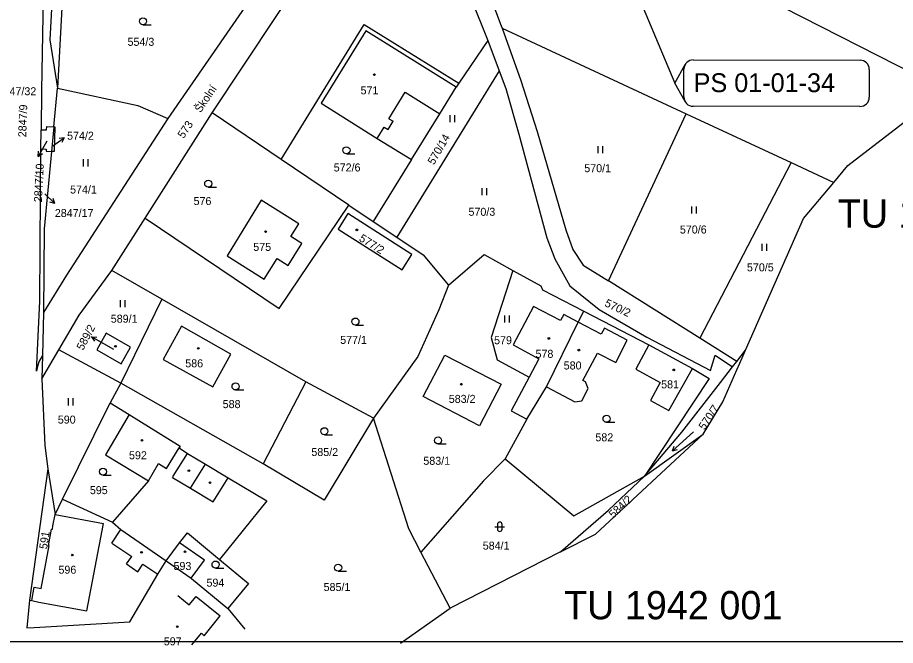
# Model space of a CAD drawing. Extents: x -558358 to -557517, y -1073785 to -1073189.
# Drawn here: x -558184.5 to -557998, y -1073784.9 to -1073651.5 of the extents above; entities that cross this region are included whole.
import ezdxf

# ---------------------------------------------------------------- set-up
doc = ezdxf.new("R2010")
doc.units = 0
for name, color, linetype in [('Hranice parcel', 7, 'Continuous'), ('Parcelní čísla', 7, 'Continuous'), ('Pop  PČ popisy', 7, 'Continuous'), ('Rozpiska_pole_1', 7, 'Continuous'), ('Rozpiska_pole_2', 7, 'Continuous'), ('Vnitřní kresba', 7, 'Continuous'), ('Vrstva 28', 7, 'Continuous'), ('Značky budov', 7, 'Continuous'), ('Značky kultur', 7, 'Continuous')]:
    doc.layers.add(name, color=color, linetype=linetype)

msp = doc.modelspace()

# ---------------------------------------------------------------- linework, layer by layer
at = {"layer": 'Hranice parcel'}
for p, q in [((-558126.57, -1073635.37), (-558152.59, -1073672.96)), ((-558047.53, -1073636.2), (-557987.38, -1073666.93)), ((-558083.83, -1073647.78), (-558081.75, -1073653.27)), ((-558081.75, -1073653.27), (-558081.56, -1073653.8)), ((-558081.56, -1073653.8), (-558042.48, -1073671.96)), ((-558084.61, -1073656.37), (-558090.78, -1073665.45)), ((-558084.61, -1073656.37), (-558082.19, -1073662.86)), ((-558082.19, -1073662.86), (-558103.95, -1073698.19)), ((-558082.19, -1073662.86), (-558080.79, -1073666.61)), ((-558090.78, -1073665.45), (-558091.34, -1073666.27)), ((-558176.83, -1073674.75), (-558176.05, -1073666.5)), ((-558008.13, -1073682.96), (-557987.38, -1073666.93)), ((-558157.39, -1073694.14), (-558143.16, -1073671.79)), ((-558128.54, -1073681.64), (-558143.16, -1073671.79)), ((-558058.98, -1073707.44), (-558042.48, -1073671.96)), ((-558042.48, -1073671.96), (-558020.18, -1073682.32)), ((-558178.3, -1073674.68), (-558176.83, -1073674.75)), ((-558176.83, -1073674.75), (-558177.33, -1073679.98)), ((-558176.83, -1073674.75), (-558176.6, -1073674.76)), ((-558176.6, -1073674.76), (-558176.71, -1073680)), ((-558179.54, -1073679.43), (-558179.49, -1073675.4)), ((-558178.45, -1073679.93), (-558177.33, -1073679.98)), ((-558176.71, -1073680), (-558177.33, -1073679.98)), ((-558114.13, -1073691.34), (-558128.54, -1073681.64)), ((-558100.81, -1073681.69), (-558108.93, -1073694.83)), ((-558020.18, -1073682.32), (-558039.55, -1073719.63)), ((-558020.18, -1073682.32), (-558011.11, -1073686.54)), ((-558011.11, -1073686.54), (-558008.13, -1073682.96)), ((-558017.53, -1073694.23), (-558011.11, -1073686.54)), ((-558114.13, -1073691.34), (-558108.93, -1073694.83)), ((-558164.46, -1073705.23), (-558157.39, -1073694.14)), ((-558108.93, -1073694.83), (-558103.95, -1073698.19)), ((-558029.85, -1073722.15), (-558017.53, -1073694.23)), ((-558153.86, -1073711.3), (-558164.46, -1073705.23)), ((-558079.26, -1073705.23), (-558083.89, -1073719.49)), ((-558039.55, -1073719.63), (-558058.98, -1073707.44)), ((-558153.86, -1073711.3), (-558162.58, -1073729.18)), ((-558123.29, -1073728.86), (-558153.86, -1073711.3)), ((-558178.98, -1073714.16), (-558179.23, -1073723.31)), ((-558065.38, -1073716.24), (-558064.19, -1073713.89)), ((-558064.19, -1073713.89), (-558050.38, -1073721.04)), ((-558072.16, -1073729.98), (-558065.38, -1073716.24)), ((-558083.89, -1073719.49), (-558082.62, -1073724.25)), ((-558031.72, -1073724.54), (-558039.55, -1073719.63)), ((-558050.38, -1073721.04), (-558041.12, -1073726.03)), ((-558179.37, -1073728.25), (-558175.74, -1073722.09)), ((-558179.23, -1073723.31), (-558179.37, -1073728.25)), ((-558162.58, -1073729.18), (-558175.74, -1073722.09)), ((-558031.72, -1073724.54), (-558029.85, -1073722.15)), ((-558082.62, -1073724.25), (-558075.83, -1073727.93)), ((-558032.62, -1073725.69), (-558031.72, -1073724.54)), ((-558162.58, -1073729.18), (-558164.87, -1073733.32)), ((-558132.34, -1073746.32), (-558162.58, -1073729.18)), ((-558123.29, -1073728.86), (-558132.34, -1073746.32)), ((-558108.92, -1073736.57), (-558123.29, -1073728.86)), ((-558076.28, -1073736.83), (-558072.16, -1073729.98)), ((-558174.95, -1073753.84), (-558164.87, -1073733.32)), ((-558164.87, -1073733.32), (-558160.79, -1073735.84)), ((-558076.28, -1073736.83), (-558080.95, -1073745.27)), ((-558061.7, -1073761.21), (-558038.85, -1073740)), ((-558051.32, -1073748.93), (-558043.37, -1073739.61)), ((-558051.32, -1073748.93), (-558038.85, -1073740)), ((-558080.95, -1073745.27), (-558085.52, -1073749.88)), ((-558178.08, -1073747.39), (-558181.97, -1073775.25)), ((-558178.08, -1073747.39), (-558176.52, -1073757.07)), ((-558058.99, -1073756.15), (-558051.32, -1073748.93)), ((-558085.52, -1073749.88), (-558098.82, -1073765.08)), ((-558176.52, -1073757.07), (-558174.95, -1073753.84)), ((-558174.95, -1073753.84), (-558164.36, -1073758.7)), ((-558069.16, -1073765.01), (-558058.99, -1073756.15)), ((-558069.16, -1073765.01), (-558061.7, -1073761.21)), ((-558152.96, -1073766.88), (-558150.14, -1073763.05)), ((-558092.62, -1073776.97), (-558098.82, -1073765.08)), ((-558069.16, -1073765.01), (-558092.62, -1073776.97)), ((-558152.96, -1073766.88), (-558147.64, -1073770.59)), ((-558147.64, -1073770.59), (-558147.54, -1073770.67)), ((-558147.54, -1073770.67), (-558139.85, -1073777.06)), ((-558181.97, -1073775.25), (-558182.51, -1073781.13)), ((-558139.85, -1073777.06), (-558136.25, -1073781.43)), ((-558103.16, -1073784.41), (-558092.62, -1073776.97)), ((-558182.51, -1073781.13), (-558181.01, -1073781.05))]:
    msp.add_line(p, q, dxfattribs=at)
for points in [[(-558086.19, -1073392.25), (-558100.56, -1073410.01), (-558117.51, -1073431.08), (-558131.78, -1073449.27), (-558138.48, -1073457.68), (-558143.38, -1073464.02), (-558146.99, -1073468.89), (-558150.46, -1073473.83), (-558152.02, -1073476.41), (-558154.26, -1073480.97), (-558156.46, -1073486.6), (-558158.91, -1073494.31), (-558160.3, -1073500.48), (-558162.16, -1073510.4), (-558165.76, -1073536.46), (-558169.94, -1073565.43), (-558173.74, -1073591.61), (-558177.66, -1073620.33), (-558178.51, -1073631.87), (-558179.02, -1073643), (-558179.24, -1073655.12), (-558179.45, -1073666.94), (-558179.49, -1073675.4)], [(-558175.82, -1073622.18), (-558177.63, -1073656.22), (-558176.05, -1073666.5)], [(-558175.82, -1073622.18), (-558174.18, -1073632.38), (-558176.05, -1073666.5)], [(-558143.16, -1073671.79), (-558122.68, -1073640.91), (-558116.74, -1073631.82), (-558110.18, -1073623.69)], [(-558110.18, -1073623.69), (-558095.16, -1073631.27), (-558088.2, -1073647.35), (-558084.61, -1073656.37)], [(-558128.54, -1073681.64), (-558110.84, -1073652.98), (-558090.78, -1073665.45)], [(-558091.34, -1073666.27), (-558110.52, -1073654.36), (-558120.01, -1073669.73), (-558108.1, -1073677.21), (-558100.81, -1073681.69)], [(-558081.56, -1073653.8), (-558077.6, -1073664.88), (-558074.09, -1073675.7), (-558068.03, -1073696.59), (-558066.56, -1073700.76), (-558064.34, -1073704.08), (-558058.98, -1073707.44)], [(-558176.05, -1073666.5), (-558158.95, -1073670.2), (-558152.59, -1073672.96)], [(-558100.81, -1073681.69), (-558094.8, -1073671.95), (-558091.34, -1073666.27)], [(-558080.79, -1073666.61), (-558077.98, -1073676.29), (-558072.03, -1073698.27), (-558070.37, -1073702.74), (-558067.15, -1073708.5), (-558060.97, -1073713.55), (-558050.8, -1073719.38), (-558037.27, -1073726.47), (-558036.33, -1073723.21), (-558032.62, -1073725.69)], [(-558152.59, -1073672.96), (-558174.12, -1073706.25), (-558178.98, -1073714.16)], [(-558179.49, -1073675.4), (-558178.35, -1073675.4), (-558178.3, -1073674.68)], [(-558180.47, -1073726.64), (-558179.79, -1073711.73), (-558179.61, -1073688.81), (-558179.54, -1073679.43)], [(-558179.54, -1073679.43), (-558178.44, -1073679.44), (-558178.45, -1073679.93)], [(-558177.33, -1073679.98), (-558178.88, -1073696.38), (-558178.98, -1073714.16)], [(-558157.39, -1073694.14), (-558128.92, -1073713.32), (-558114.13, -1073691.34)], [(-558124.75, -1073695.3), (-558132.74, -1073690.28), (-558139.98, -1073702.13), (-558132.13, -1073707.05), (-558129.35, -1073702.69), (-558127, -1073704.15), (-558124.1, -1073699.49), (-558126.45, -1073698.03), (-558124.75, -1073695.3)], [(-558114.32, -1073693.16), (-558116.42, -1073696.46), (-558102.81, -1073705.11), (-558100.72, -1073701.82), (-558114.32, -1073693.16)], [(-558103.95, -1073698.19), (-558098.36, -1073701.95), (-558092.97, -1073708.36)], [(-558092.97, -1073708.36), (-558085.4, -1073701.82), (-558079.26, -1073705.23)], [(-558175.74, -1073722.09), (-558171.39, -1073714.72), (-558164.46, -1073705.23)], [(-558079.26, -1073705.23), (-558073.37, -1073708.51), (-558073.01, -1073709.33), (-558064.19, -1073713.89)], [(-558092.97, -1073708.36), (-558095.02, -1073713.61), (-558099.46, -1073723.54), (-558108.92, -1073736.57)], [(-558065.38, -1073716.24), (-558068.48, -1073714.62), (-558069.13, -1073715.86), (-558074.89, -1073712.87), (-558079.25, -1073721.04), (-558073.73, -1073723.99), (-558075.83, -1073727.93)], [(-558072.16, -1073729.98), (-558066.15, -1073733.15), (-558064.66, -1073732.92), (-558063.26, -1073730.33), (-558063.88, -1073728.9), (-558064.4, -1073728.63), (-558061.31, -1073722.78), (-558057.44, -1073724.76), (-558054.98, -1073720.06), (-558059.84, -1073717.49), (-558060.51, -1073718.77), (-558065.38, -1073716.24)], [(-558139.17, -1073722.99), (-558149.67, -1073717.07), (-558153.56, -1073724.14), (-558143.05, -1073729.97), (-558139.17, -1073722.99)], [(-558160.49, -1073721.53), (-558165.71, -1073718.57), (-558167.69, -1073722.06), (-558162.47, -1073725.03), (-558160.49, -1073721.53)], [(-558050.38, -1073721.04), (-558053.17, -1073726.18), (-558047.96, -1073729.01), (-558050.05, -1073732.86), (-558046.14, -1073734.98), (-558041.12, -1073726.03)], [(-558179.23, -1073723.31), (-558179.97, -1073724.66), (-558180.29, -1073725.65), (-558180.47, -1073726.64)], [(-558081.79, -1073729.39), (-558086.39, -1073738.22), (-558098.32, -1073732.01), (-558093.7, -1073723.21), (-558081.79, -1073729.39)], [(-558031.69, -1073726.31), (-558031.08, -1073724.94), (-558029.85, -1073722.15)], [(-558041.12, -1073726.03), (-558037.61, -1073728.19), (-558051.32, -1073748.93)], [(-558043.37, -1073739.61), (-558035.2, -1073729), (-558032.62, -1073725.69)], [(-558038.85, -1073740), (-558034.7, -1073733.14), (-558031.69, -1073726.31)], [(-558179.37, -1073728.25), (-558178.74, -1073742.4), (-558178.08, -1073747.39)], [(-558075.83, -1073727.93), (-558079.61, -1073735.04), (-558076.28, -1073736.83)], [(-558160.79, -1073735.84), (-558165.86, -1073744.39), (-558156.72, -1073749.9), (-558164.36, -1073758.7)], [(-558160.79, -1073735.84), (-558149.94, -1073742.55), (-558150.18, -1073742.93), (-558148.38, -1073744.09), (-558144.55, -1073746.39), (-558139.78, -1073749.25), (-558131.58, -1073754.18), (-558141.63, -1073766.63)], [(-558108.92, -1073736.57), (-558119.39, -1073754.05), (-558132.34, -1073746.32)], [(-558098.82, -1073765.08), (-558101.41, -1073760.13), (-558108.92, -1073736.57)], [(-558080.95, -1073745.27), (-558066.32, -1073757.38), (-558051.32, -1073748.93)], [(-558181.97, -1073775.25), (-558181.48, -1073775.34), (-558180.95, -1073772.5), (-558179.48, -1073772.78), (-558177.77, -1073763.68), (-558177.92, -1073763.66), (-558177.27, -1073760.18), (-558177.12, -1073760.21), (-558177.05, -1073759.47), (-558176.52, -1073757.07)], [(-558164.36, -1073758.7), (-558162.58, -1073760.28), (-558152.96, -1073766.88)], [(-558150.14, -1073763.05), (-558148.43, -1073760.98), (-558141.63, -1073766.63)], [(-558147.64, -1073770.59), (-558144.77, -1073766.75), (-558150.14, -1073763.05)], [(-558181.01, -1073781.05), (-558160.65, -1073779.83), (-558154.69, -1073769.71), (-558152.96, -1073766.88)], [(-558141.63, -1073766.63), (-558135.48, -1073771.74), (-558139.85, -1073777.06)]]:
    msp.add_lwpolyline(points, dxfattribs=at)
at = {"layer": 'Pop  PČ popisy'}
for p, q in [((-558177.05, -1073678.78), (-558174.59, -1073677.06)), ((-558174.59, -1073677.06), (-558175.7, -1073677.22)), ((-558174.59, -1073677.06), (-558175.12, -1073678.04)), ((-558178.66, -1073678.4), (-558180.11, -1073681.02)), ((-558178.32, -1073677.78), (-558178.66, -1073678.4)), ((-558180.11, -1073681.02), (-558180.07, -1073679.91)), ((-558180.11, -1073681.02), (-558179.19, -1073680.39)), ((-558178.75, -1073688.95), (-558176.59, -1073691.03)), ((-558176.59, -1073691.03), (-558176.96, -1073689.98)), ((-558176.59, -1073691.03), (-558177.66, -1073690.7)), ((-558166.16, -1073720.8), (-558168.79, -1073719.34)), ((-558168.79, -1073719.34), (-558167.67, -1073719.39)), ((-558168.79, -1073719.34), (-558168.15, -1073720.27)), ((-558164.05, -1073721.99), (-558166.16, -1073720.8))]:
    msp.add_line(p, q, dxfattribs=at)
at = {"layer": 'Rozpiska_pole_1'}
msp.add_line((-557516.53, -1073784.09), (-558357.53, -1073784.09), dxfattribs=at)
at = {"layer": 'Vnitřní kresba'}
for p, q in [((-558105.6, -1073673.04), (-558102.19, -1073667.36)), ((-558102.19, -1073667.36), (-558094.8, -1073671.95)), ((-558105.6, -1073673.04), (-558104.74, -1073673.55)), ((-558108.1, -1073677.21), (-558106.65, -1073674.8)), ((-558106.65, -1073674.8), (-558105.79, -1073675.32)), ((-558105.79, -1073675.32), (-558104.74, -1073673.55)), ((-558152.86, -1073747.27), (-558150.18, -1073742.93)), ((-558151.46, -1073748.94), (-558148.38, -1073744.09)), ((-558156.72, -1073749.9), (-558154.56, -1073746.22)), ((-558154.56, -1073746.22), (-558152.86, -1073747.27)), ((-558147.74, -1073751.5), (-558144.55, -1073746.39)), ((-558151.61, -1073749.2), (-558151.46, -1073748.94)), ((-558151.61, -1073749.2), (-558147.74, -1073751.5)), ((-558142.92, -1073754.36), (-558139.78, -1073749.25)), ((-558147.74, -1073751.5), (-558142.92, -1073754.36)), ((-558176.52, -1073757.07), (-558166.27, -1073759.01)), ((-558169.76, -1073777.52), (-558166.27, -1073759.01)), ((-558164.5, -1073763.14), (-558162.58, -1073760.28)), ((-558164.5, -1073763.14), (-558160.25, -1073766.01)), ((-558161.38, -1073767.55), (-558160.25, -1073766.01)), ((-558161.38, -1073767.55), (-558158.98, -1073769.26)), ((-558158.98, -1073769.26), (-558157.87, -1073767.62)), ((-558157.87, -1073767.62), (-558154.69, -1073769.71)), ((-558181.48, -1073775.34), (-558180, -1073775.65)), ((-558180, -1073775.65), (-558169.76, -1073777.52)), ((-558150.48, -1073774.29), (-558148.03, -1073776.28)), ((-558148.03, -1073776.28), (-558146.55, -1073774.45)), ((-558146.55, -1073774.45), (-558141.43, -1073778.61)), ((-558144.83, -1073782.8), (-558141.43, -1073778.61)), ((-558147.47, -1073784.78), (-558145.45, -1073782.3)), ((-558145.45, -1073782.3), (-558144.83, -1073782.8))]:
    msp.add_line(p, q, dxfattribs=at)
at = {"layer": 'Vrstva 28'}
for p, q in [((-558150.16, -1073413.05), (-558044.9, -1073665.43)), ((-558044.9, -1073665.43), (-558042.67, -1073661.51)), ((-558040.96, -1073660.51), (-558005.53, -1073660.57)), ((-558042.94, -1073668.38), (-558042.93, -1073662.48)), ((-558003.56, -1073662.54), (-558003.57, -1073668.45)), ((-558042.68, -1073669.35), (-558044.9, -1073665.43)), ((-558005.54, -1073670.41), (-558040.97, -1073670.36))]:
    msp.add_line(p, q, dxfattribs=at)
for centre, start, end in [((-558040.96, -1073662.48), 89.9095, 179.9095), ((-558005.53, -1073662.54), 359.9095, 89.9095), ((-558040.97, -1073668.39), 179.9095, 269.9095), ((-558005.54, -1073668.44), 269.9095, 359.9095)]:
    msp.add_arc(centre, 1.97, start, end, dxfattribs=at)
at = {"layer": 'Značky budov'}
for centre in [(-558108.71, -1073663.65), (-558131.8, -1073696.98), (-558112.42, -1073696.62), (-558071.63, -1073719.68), (-558163.71, -1073721.34), (-558146.11, -1073721.79), (-558065.25, -1073722.15), (-558045.1, -1073726.35), (-558090.22, -1073729.39), (-558158.06, -1073741.3), (-558148.12, -1073747.76), (-558143.62, -1073750.31), (-558172.89, -1073765.67), (-558158.17, -1073765.09), (-558148.92, -1073764.99), (-558150.58, -1073780.89)]:
    msp.add_circle(centre, 0.175, dxfattribs=at)
at = {"layer": 'Značky kultur'}
for p, q in [((-558157.86, -1073653.06), (-558156.11, -1073653.06)), ((-558092.63, -1073673.76), (-558092.63, -1073672.26)), ((-558091.63, -1073673.76), (-558091.63, -1073672.26)), ((-558061.16, -1073680.32), (-558061.16, -1073678.82)), ((-558060.16, -1073680.32), (-558060.16, -1073678.82)), ((-558114.63, -1073680.46), (-558112.88, -1073680.46)), ((-558170.5, -1073683.13), (-558170.5, -1073681.63)), ((-558169.5, -1073683.13), (-558169.5, -1073681.63)), ((-558144, -1073687.55), (-558142.25, -1073687.55)), ((-558085.83, -1073689.23), (-558085.83, -1073687.73)), ((-558084.83, -1073689.23), (-558084.83, -1073687.73)), ((-558041.24, -1073693.17), (-558041.24, -1073691.67)), ((-558040.24, -1073693.17), (-558040.24, -1073691.67)), ((-558026.3, -1073701.09), (-558026.3, -1073699.59)), ((-558025.3, -1073701.09), (-558025.3, -1073699.59)), ((-558162.67, -1073713.05), (-558162.67, -1073711.55)), ((-558161.67, -1073713.05), (-558161.67, -1073711.55)), ((-558080.99, -1073716.31), (-558080.99, -1073714.81)), ((-558079.99, -1073716.31), (-558079.99, -1073714.81)), ((-558112.73, -1073716.84), (-558110.98, -1073716.84)), ((-558138.2, -1073730.62), (-558136.45, -1073730.62)), ((-558173.68, -1073733.89), (-558173.68, -1073732.39)), ((-558172.68, -1073733.89), (-558172.68, -1073732.39)), ((-558059.37, -1073737.48), (-558057.62, -1073737.48)), ((-558119.32, -1073740.13), (-558117.57, -1073740.13)), ((-558040.91, -1073739.54), (-558045.37, -1073743.55)), ((-558095.17, -1073742.09), (-558093.42, -1073742.09)), ((-558045.37, -1073743.55), (-558044.98, -1073742.53)), ((-558045.37, -1073743.55), (-558044.31, -1073743.27)), ((-558166.36, -1073748.71), (-558164.61, -1073748.71)), ((-558083.08, -1073759.67), (-558081.08, -1073759.67)), ((-558082.58, -1073759.17), (-558082.58, -1073760.17)), ((-558081.58, -1073760.17), (-558081.58, -1073759.17)), ((-558142.44, -1073768.45), (-558140.69, -1073768.45)), ((-558116.4, -1073769.12), (-558114.65, -1073769.12))]:
    msp.add_line(p, q, dxfattribs=at)
for centre in [(-558157.86, -1073652.31), (-558114.63, -1073679.71), (-558144, -1073686.8), (-558112.73, -1073716.09), (-558138.2, -1073729.87), (-558059.37, -1073736.73), (-558119.32, -1073739.38), (-558095.17, -1073741.34), (-558166.36, -1073747.96), (-558142.44, -1073767.7), (-558116.4, -1073768.37)]:
    msp.add_circle(centre, 0.75, dxfattribs=at)
for centre, start, end in [((-558082.08, -1073759.17), 0, 180), ((-558082.08, -1073760.17), 180, 359.9879)]:
    msp.add_arc(centre, 0.5, start, end, dxfattribs=at)

# ---------------------------------------------------------------- texts
at = {"layer": 'Parcelní čísla'}
for s, p in [('554/3', (-558161.15, -1073657.52)), ('2847/32', (-558188.75, -1073668.02)), ('571', (-558111.64, -1073667.83)), ('574/2', (-558173.99, -1073677.47)), ('572/6', (-558117.34, -1073684.21)), ('570/1', (-558064.11, -1073684.36)), ('574/1', (-558173.35, -1073688.89)), ('576', (-558147.12, -1073691.34)), ('570/3', (-558088.71, -1073693.62)), ('2847/17', (-558176.59, -1073693.88)), ('570/6', (-558043.8, -1073697.39)), ('575', (-558134.43, -1073701.08)), ('570/5', (-558029.55, -1073705.42)), ('589/1', (-558164.71, -1073716.33)), ('577/1', (-558115.97, -1073720.83)), ('579', (-558083.27, -1073720.9)), ('578', (-558074.47, -1073723.79)), ('586', (-558148.88, -1073725.81)), ('580', (-558068.48, -1073726.26)), ('581', (-558047.78, -1073730.27)), ('588', (-558140.93, -1073734.47)), ('583/2', (-558092.9, -1073733.36)), ('590', (-558175.96, -1073737.76)), ('582', (-558061.75, -1073741.52)), ('592', (-558160.83, -1073745.33)), ('585/2', (-558122.09, -1073744.64)), ('583/1', (-558098.3, -1073746.51)), ('595', (-558169.15, -1073752.74)), ('584/1', (-558085.68, -1073764.52)), ('596', (-558175.82, -1073769.64)), ('593', (-558151.38, -1073768.85)), ('594', (-558144.37, -1073772.39)), ('585/1', (-558119.49, -1073773.32)), ('597', (-558153.44, -1073784.85))]:
    msp.add_text(s, height=1.7, dxfattribs=at).set_placement(p)
for s, rotation, p in [('2847/9', 88, (-558182.68, -1073676.97)), ('573', 56, (-558149.24, -1073677.32)), ('570/14', 60, (-558096.05, -1073682.93)), ('2847/10', 87, (-558179.35, -1073690.79)), ('577/2', 328, (-558112.11, -1073698.84)), ('570/2', 335, (-558059.92, -1073712.75)), ('589/2', 62, (-558170.6, -1073722.33)), ('570/7', 56, (-558038.56, -1073739.25)), ('584/2', 43, (-558057.95, -1073757.95)), ('591', 81, (-558178.26, -1073764.52))]:
    msp.add_text(s, height=1.7, rotation=rotation, dxfattribs=at).set_placement(p)
at = {"layer": 'Pop  PČ popisy'}
msp.add_text('Školní', height=1.7, rotation=56, dxfattribs=at).set_placement((-558145.62, -1073671.85))
at = {"layer": 'Rozpiska_pole_2'}
for s, p in [('TU 1942 002', (-558010.26, -1073696.15)), ('TU 1942 001', (-558068.41, -1073779.32))]:
    msp.add_text(s, height=6, dxfattribs=at).set_placement(p)
at = {"layer": 'Vrstva 28'}
msp.add_text('PS 01-01-34', height=4, dxfattribs=at).set_placement((-558040.87, -1073667.36))

doc.saveas('drawing.dxf')
